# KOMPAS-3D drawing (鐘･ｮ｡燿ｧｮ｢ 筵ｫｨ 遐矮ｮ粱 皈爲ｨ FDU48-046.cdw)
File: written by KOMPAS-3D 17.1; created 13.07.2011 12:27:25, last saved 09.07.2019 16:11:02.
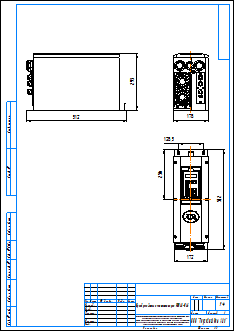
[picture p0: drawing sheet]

Sheet 1: A3, portrait

Title block, sheet 1: name: Преобразователи частоты серии FDU48-046; scale: 1:4; sheets: 1; sheet format: A3; stored path: \\adlc.lan\data\АДЛ_ПКД\3D-модели\Поставщики\Оборудование Emotron\Преобразователи частоты\Серия FDU 2.0\KOMPAS 2D\Преобразователи частоты серии FDU48-046.cdw

Views: Спереди 1
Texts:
  Рама для чертежей
  Лит-Масса-Масштаб
  Материал-Предприятие
  Масштаб
  Изм.
  Лист
  № докум.
  Подп.
  Дата
  Лит.
  Разраб.
  Пров.
  Т.контр.
  Листов
  Внимание! Данный продукт является объектом авторского права ООО «Торговый Дом АДЛ».
  Запрещается изменение, копирование, распространение
  (в том числе путем копирования на другие сайты и ресурсы в Интернете)
  или любое иное использование информации и объектов без предварительного
  согласия правообладателя (ООО «Торговый Дом АДЛ»).
  Н.контр.
  Утв.
  ООО "Торговый дом АДЛ"
  Изменение
  Номер документа
  Подпись
  Обозначение документа
  Наименование изделия
  Масса изделия по ГОСТ 2.109-73
  Порядковый номер листа
  Общее количество листов в документе
  Характер работы, выполненной лицом, подписавшим документ
  Наименование или индекс предприятия, выпускающего документ
  Инв. № подл.
  Подп. и дата
  Взам. инв. №
  Инв. № дубл.
  Инвентарный номер подлинника по ГОСТ 2.501-68
  Подпись принявшего подлинник в отдел технической документации
  Инвентарный номер подлинника, взамен которого выпущен данный подлинник
  Инвентарный номер дубликата по ГОСТ 2.502-68
  Подпись принявшего дубликат в отдел технической документации
  Справ. №
  Перв. примен.
  Обозначение документа, взамен или на основании которого выпущен данный документ
  Обозначение документа, в котором впервые записан данный документ
  Подпись лица, копировавшего чертеж
  Обозначение формата листа
  !Рама для чертежа
Dimensions and other numbers on the sheet: 178; 512; 128,5; 172; 293; 256; 1:4; 1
